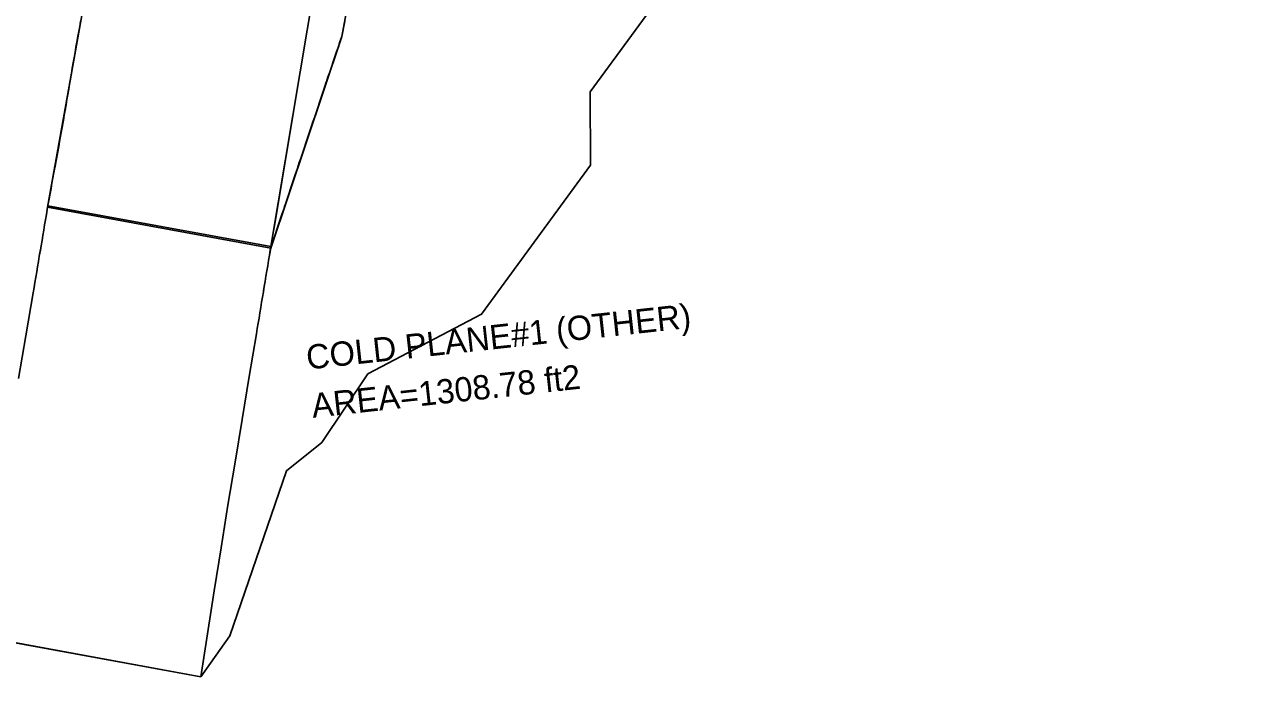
# Model space of a CAD drawing. Extents: x 1509538 to 1510847, y 401283 to 402022.
# Drawn here: x 1509743.9 to 1509883.9, y 401344.6 to 401419.8 of the extents above; entities that cross this region are included whole.
import ezdxf

# ---------------------------------------------------------------- set-up
doc = ezdxf.new("R2010")
doc.units = 0
for name, color, linetype in [('LAWE_P_T', 7, 'Continuous'), ('Level 1', 7, 'Continuous'), ('Level 10', 7, 'Continuous'), ('Level 2', 7, 'Continuous'), ('Level 24', 7, 'Continuous'), ('Level 3', 7, 'Continuous'), ('Level 7', 7, 'Continuous'), ('PCH_P', 7, 'Continuous')]:
    doc.layers.add(name, color=color, linetype=linetype)

msp = doc.modelspace()

# ---------------------------------------------------------------- linework, layer by layer
at = {"layer": 'Level 1'}
for p, q in [((1509772.28, 401394.01), (1509746.6, 401398.71)), ((1509772.28, 401394.01), (1509746.6, 401398.71)), ((1509738.43, 401349.37), (1509764.23, 401344.65)), ((1509738.43, 401349.37), (1509764.23, 401344.65))]:
    msp.add_line(p, q, dxfattribs=at)
for points in [[(1509746.6, 401398.71), (1509746.56, 401398.48), (1509746.46, 401397.88), (1509746.36, 401397.27), (1509746.25, 401396.67), (1509746.15, 401396.07), (1509746.05, 401395.47), (1509745.95, 401394.87), (1509745.85, 401394.27), (1509745.76, 401393.77), (1509745.74, 401393.66), (1509745.64, 401393.06), (1509745.54, 401392.46), (1509745.44, 401391.86), (1509745.34, 401391.25), (1509745.23, 401390.65), (1509745.13, 401390.05), (1509745.03, 401389.45), (1509744.93, 401388.84), (1509744.09, 401383.91), (1509743.26, 401378.98)], [(1509746.6, 401398.71), (1509746.46, 401397.88), (1509746.36, 401397.27), (1509746.25, 401396.67), (1509746.15, 401396.07), (1509746.05, 401395.47), (1509745.95, 401394.87), (1509745.85, 401394.27), (1509745.76, 401393.77), (1509745.64, 401393.06), (1509745.54, 401392.46), (1509745.44, 401391.86), (1509745.34, 401391.25), (1509745.23, 401390.65), (1509745.13, 401390.05), (1509745.03, 401389.45), (1509744.93, 401388.84), (1509744.09, 401383.91), (1509743.26, 401378.98)], [(1509764.23, 401344.65), (1509765.01, 401349.59), (1509765.79, 401354.53), (1509766.58, 401359.47), (1509767.36, 401364.41), (1509768.18, 401369.34), (1509769, 401374.27), (1509769.82, 401379.21), (1509770.64, 401384.14), (1509770.74, 401384.74), (1509770.84, 401385.35), (1509770.94, 401385.95), (1509771.04, 401386.55), (1509771.14, 401387.15), (1509771.24, 401387.76), (1509771.34, 401388.36), (1509771.44, 401388.96), (1509771.46, 401389.07), (1509771.54, 401389.56), (1509771.64, 401390.16), (1509771.74, 401390.77), (1509771.84, 401391.37), (1509771.94, 401391.97), (1509772.04, 401392.57), (1509772.14, 401393.18), (1509772.24, 401393.78), (1509772.28, 401394.01)], [(1509764.23, 401344.65), (1509765.01, 401349.59), (1509765.79, 401354.53), (1509766.58, 401359.47), (1509767.36, 401364.41), (1509768.18, 401369.34), (1509769, 401374.27), (1509769.82, 401379.21), (1509770.64, 401384.14), (1509770.74, 401384.74), (1509770.84, 401385.35), (1509770.94, 401385.95), (1509771.04, 401386.55), (1509771.14, 401387.15), (1509771.24, 401387.76), (1509771.34, 401388.36), (1509771.44, 401388.96), (1509771.54, 401389.56), (1509771.64, 401390.16), (1509771.74, 401390.77), (1509771.84, 401391.37), (1509771.94, 401391.97), (1509772.04, 401392.57), (1509772.14, 401393.18), (1509772.28, 401394.01)]]:
    msp.add_lwpolyline(points, dxfattribs=at)
at = {"layer": 'Level 10'}
for p, q in [((1509747.54, 401403.89), (1509747.49, 401403.62)), ((1509746.67, 401399.08), (1509746.6, 401398.71)), ((1509746.6, 401398.71), (1509772.28, 401394.01)), ((1509772.54, 401395.58), (1509772.64, 401396.18))]:
    msp.add_line(p, q, dxfattribs=at)
for points in [[(1509772.64, 401396.18), (1509772.74, 401396.79), (1509775.66, 401414.3), (1509783.79, 401462.54)], [(1509750.39, 401420.13), (1509750.29, 401419.53), (1509750.18, 401418.93), (1509750.08, 401418.4), (1509749.96, 401417.72), (1509749.86, 401417.12), (1509749.76, 401416.52), (1509749.65, 401415.92), (1509749.55, 401415.32), (1509749.44, 401414.71), (1509749.34, 401414.11), (1509749.24, 401413.51), (1509749.13, 401412.91), (1509749.03, 401412.31), (1509748.93, 401411.7), (1509748.82, 401411.1), (1509748.72, 401410.5), (1509748.61, 401409.9), (1509748.51, 401409.3), (1509748.41, 401408.7), (1509748.38, 401408.55), (1509748.2, 401407.49), (1509748.09, 401406.89), (1509747.98, 401406.29), (1509747.87, 401405.69), (1509747.76, 401405.09), (1509747.65, 401404.49), (1509747.54, 401403.89)], [(1509747.49, 401403.62), (1509747.32, 401402.69), (1509747.21, 401402.09), (1509747.1, 401401.48), (1509746.99, 401400.88), (1509746.88, 401400.28), (1509746.77, 401399.68), (1509746.67, 401399.08)], [(1509772.28, 401394.01), (1509772.44, 401394.98), (1509772.54, 401395.58)]]:
    msp.add_lwpolyline(points, dxfattribs=at)
at = {"layer": 'Level 2'}
for p, q in [((1509746.6, 401398.71), (1509772.28, 401394.01)), ((1509746.63, 401398.87), (1509772.31, 401394.18)), ((1509772.54, 401395.58), (1509772.64, 401396.18))]:
    msp.add_line(p, q, dxfattribs=at)
for points in [[(1509772.31, 401394.18), (1509775.66, 401414.3), (1509783.79, 401462.54), (1509792.46, 401505.8), (1509800.22, 401536.88), (1509802.51, 401540.8)], [(1509772.64, 401396.18), (1509772.74, 401396.79), (1509775.66, 401414.3), (1509783.79, 401462.54)], [(1509750.39, 401420.13), (1509750.29, 401419.53), (1509750.18, 401418.93), (1509750.08, 401418.4), (1509750.07, 401418.32), (1509749.96, 401417.72), (1509749.86, 401417.12), (1509749.76, 401416.52), (1509749.65, 401415.92), (1509749.55, 401415.32), (1509749.44, 401414.71), (1509749.34, 401414.11), (1509749.24, 401413.51), (1509749.23, 401413.47), (1509749.13, 401412.91), (1509749.03, 401412.31), (1509748.93, 401411.7), (1509748.82, 401411.1), (1509748.72, 401410.5), (1509748.61, 401409.9), (1509748.51, 401409.3), (1509748.41, 401408.7), (1509748.38, 401408.55), (1509748.3, 401408.09), (1509748.2, 401407.49), (1509748.09, 401406.89), (1509747.98, 401406.29), (1509747.87, 401405.69), (1509747.76, 401405.09), (1509747.65, 401404.49), (1509747.54, 401403.89), (1509747.49, 401403.62), (1509747.43, 401403.29), (1509747.32, 401402.69), (1509747.21, 401402.09), (1509747.1, 401401.48), (1509746.99, 401400.88), (1509746.88, 401400.28), (1509746.77, 401399.68), (1509746.67, 401399.08), (1509746.63, 401398.87)], [(1509750.39, 401420.13), (1509750.29, 401419.53), (1509750.18, 401418.93), (1509750.08, 401418.4), (1509749.96, 401417.72), (1509749.86, 401417.12), (1509749.76, 401416.52), (1509749.65, 401415.92), (1509749.55, 401415.32), (1509749.44, 401414.71), (1509749.34, 401414.11), (1509749.24, 401413.51), (1509749.13, 401412.91), (1509749.03, 401412.31), (1509748.93, 401411.7), (1509748.82, 401411.1), (1509748.72, 401410.5), (1509748.61, 401409.9), (1509748.51, 401409.3), (1509748.41, 401408.7), (1509748.38, 401408.55), (1509748.2, 401407.49), (1509748.09, 401406.89), (1509747.98, 401406.29), (1509747.87, 401405.69), (1509747.76, 401405.09), (1509747.65, 401404.49), (1509747.54, 401403.89)], [(1509747.49, 401403.62), (1509747.32, 401402.69), (1509747.21, 401402.09), (1509747.1, 401401.48), (1509746.99, 401400.88), (1509746.88, 401400.28), (1509746.77, 401399.68), (1509746.67, 401399.08)], [(1509747.54, 401403.89), (1509747.49, 401403.62)], [(1509746.67, 401399.08), (1509746.6, 401398.71)], [(1509772.28, 401394.01), (1509772.44, 401394.98), (1509772.54, 401395.58)]]:
    msp.add_lwpolyline(points, dxfattribs=at)
at = {"layer": 'Level 24'}
msp.add_lwpolyline([(1509829.75, 401765.91), (1509866.1, 401667.73), (1509876.61, 401577.47), (1509875.57, 401568.19), (1509883.85, 401563.18), (1509866.77, 401506.88), (1509856.53, 401476.73), (1509809.07, 401412), (1509809.1, 401403.54), (1509796.56, 401386.39), (1509783.48, 401379.52), (1509778.17, 401371.6), (1509774.1, 401368.36), (1509767.58, 401349.35), (1509764.23, 401344.65), (1509737.94, 401349.46)], dxfattribs=at)
at = {"layer": 'Level 3'}
for p, q in [((1509775.66, 401414.3), (1509772.31, 401394.18)), ((1509772.31, 401394.18), (1509772.33, 401394.17)), ((1509772.33, 401394.17), (1509772.4, 401394.37))]:
    msp.add_line(p, q, dxfattribs=at)
for points in [[(1509792.46, 401505.8), (1509783.79, 401462.54), (1509775.66, 401414.3)], [(1509772.4, 401394.37), (1509772.6, 401394.96), (1509772.79, 401395.54), (1509772.99, 401396.13), (1509773.19, 401396.71), (1509773.38, 401397.3), (1509773.58, 401397.88), (1509773.78, 401398.47), (1509773.89, 401398.79), (1509773.97, 401399.05), (1509774.17, 401399.64), (1509774.37, 401400.22), (1509774.56, 401400.81), (1509774.76, 401401.39), (1509774.95, 401401.97), (1509775.15, 401402.56), (1509775.35, 401403.15), (1509775.5, 401403.58), (1509775.54, 401403.73), (1509775.74, 401404.32), (1509775.94, 401404.9), (1509776.13, 401405.48), (1509776.33, 401406.07), (1509776.52, 401406.66), (1509776.72, 401407.24), (1509776.92, 401407.82), (1509777.1, 401408.37), (1509777.11, 401408.41), (1509777.31, 401408.99), (1509777.51, 401409.58), (1509777.7, 401410.16), (1509777.9, 401410.75), (1509778.1, 401411.33), (1509778.29, 401411.92), (1509778.49, 401412.5), (1509778.68, 401413.09), (1509778.71, 401413.16), (1509778.88, 401413.67), (1509779.08, 401414.26), (1509779.28, 401414.84), (1509779.47, 401415.43), (1509779.67, 401416.01), (1509779.87, 401416.6), (1509780.07, 401417.18), (1509780.26, 401417.77), (1509780.33, 401417.95), (1509780.48, 401418.35), (1509780.59, 401418.95), (1509780.7, 401419.55), (1509780.81, 401420.15)]]:
    msp.add_lwpolyline(points, dxfattribs=at)
at = {"layer": 'Level 7'}
for p, q in [((1509792.24, 401482.62), (1509780.48, 401418.35)), ((1509792.24, 401482.62), (1509780.48, 401418.35)), ((1509746.6, 401398.71), (1509752.45, 401431.55)), ((1509746.6, 401398.71), (1509752.45, 401431.55)), ((1509780.48, 401418.35), (1509772.28, 401394.01)), ((1509780.48, 401418.35), (1509772.28, 401394.01)), ((1509772.28, 401394.01), (1509746.6, 401398.71)), ((1509772.28, 401394.01), (1509746.6, 401398.71))]:
    msp.add_line(p, q, dxfattribs=at)
at = {"layer": 'PCH_P'}
msp.add_line((1509772.28, 401394.01), (1509746.6, 401398.71), dxfattribs=at)

# ---------------------------------------------------------------- texts
at = {"layer": 'LAWE_P_T'}
for s, p in [('COLD PLANE#1 (OTHER)', (1509776.53, 401380.01)), ('AREA=1308.78 ft2', (1509777.14, 401374.45))]:
    msp.add_text(s, height=2.8, rotation=6.2219, dxfattribs=at).set_placement(p)

doc.saveas('drawing.dxf')
